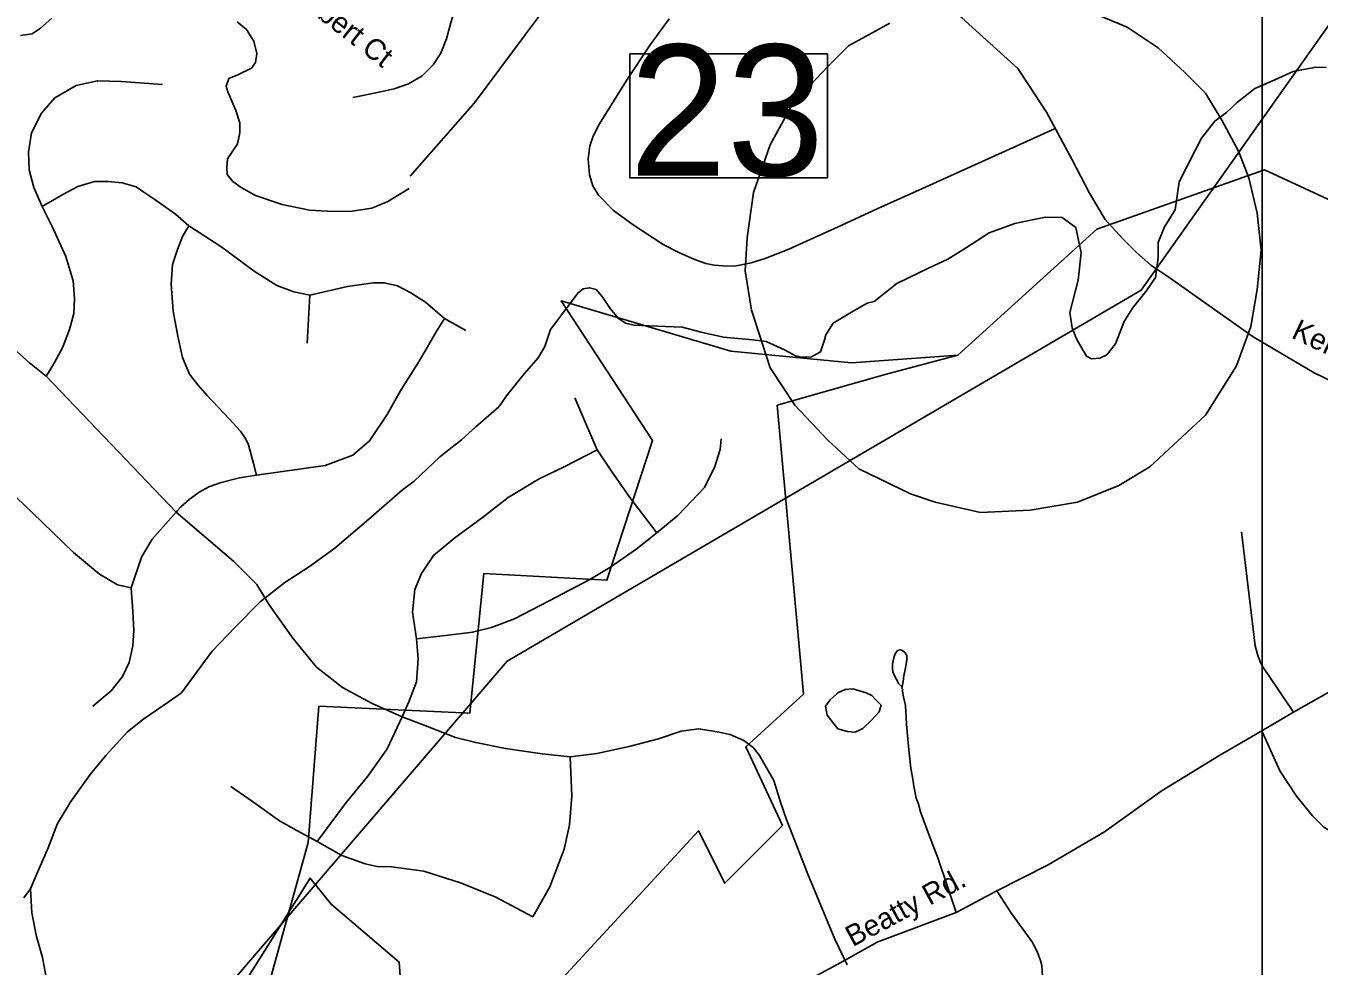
# Model space of a CAD drawing. Extents: x 1268485 to 1426702, y 514839 to 616766.
# Drawn here: x 1364164 to 1368211, y 535006 to 537948 of the extents above; entities that cross this region are included whole.
import ezdxf

# ---------------------------------------------------------------- set-up
doc = ezdxf.new("R2010")
doc.units = 0
for name, color, linetype in [('Old_Level_10', 7, 'Continuous'), ('Old_Level_11', 7, 'Continuous'), ('Old_Level_3', 7, 'Continuous'), ('Old_Level_31', 7, 'Continuous'), ('Old_Level_32', 7, 'Continuous'), ('Old_Level_35', 7, 'Continuous'), ('Old_Level_48', 7, 'Continuous'), ('Old_Level_49', 7, 'Continuous'), ('Old_Level_50', 7, 'Continuous'), ('Old_Level_56', 7, 'Continuous'), ('Old_Level_59', 7, 'Continuous'), ('Old_Level_62', 7, 'Continuous'), ('Old_Level_63', 7, 'Continuous')]:
    doc.layers.add(name, color=color, linetype=linetype)

msp = doc.modelspace()

# ---------------------------------------------------------------- linework, layer by layer
at = {"layer": 'Old_Level_3'}
for points in [[(1367151.529, 536425.852), (1367306.529, 536432.31), (1367455.071, 536458.143), (1367584.237, 536509.81), (1367681.112, 536567.935), (1367855.487, 536729.394), (1367952.362, 536884.393), (1367997.57, 537007.102), (1368016.945, 537123.352), (1368029.862, 537246.06), (1368016.945, 537362.31), (1367991.112, 537472.102), (1367958.821, 537556.06), (1367907.154, 537652.935), (1367855.487, 537736.893), (1367790.903, 537801.477), (1367706.945, 537878.977), (1367610.07, 537943.56), (1367487.362, 537995.227)], [(1366867.362, 537956.477), (1366738.195, 537885.436), (1366673.612, 537820.852), (1366563.82, 537704.602), (1366492.778, 537575.435), (1366441.112, 537426.893), (1366421.737, 537284.81), (1366415.279, 537181.477), (1366434.654, 537058.769), (1366492.778, 536877.935), (1366570.278, 536761.685), (1366673.612, 536651.894), (1366770.487, 536561.477), (1366931.945, 536483.977), (1367009.445, 536458.143), (1367151.529, 536425.852)]]:
    msp.add_lwpolyline(points, dxfattribs=at)
at = {"layer": 'Old_Level_31'}
msp.add_line((1367691.483, 537149.381), (1367691.483, 537149.381), dxfattribs=at)
msp.add_lwpolyline([(1366054.207, 537860.024), (1366672.4, 537860.024), (1366672.4, 537472.278), (1366054.207, 537472.278), (1366054.207, 537860.024)], dxfattribs=at)
at = {"layer": 'Old_Level_32'}
for points in [[(1366801.236, 538688.336), (1366842.188, 538636.437), (1366864.029, 538581.806), (1366880.409, 538529.908), (1366896.528, 538459.074), (1366921.223, 538360.896), (1367003.265, 538115.264), (1367060.596, 538014.198), (1367093.358, 537973.226), (1367268.085, 537814.798), (1367300.847, 537765.63), (1367358.179, 537678.222), (1367438.695, 537528.693), (1367492.959, 537424.647), (1367541.267, 537342.316), (1367596.733, 537281.462), (1367639.674, 537238.507), (1367684.405, 537199.131), (1367738.082, 537163.335), (1368004.675, 536975.405), (1368196.122, 536862.648), (1368550.387, 536690.827)], [(1368032.196, 535742.385), (1368131.081, 535800.326), (1368518.18, 536019.65), (1368682.789, 536123.459), (1368857.781, 536236.815), (1368986.956, 536304.229), (1369144.407, 536366.872)], [(1365594.581, 533858.966), (1365633.814, 533978.307), (1365703.731, 534164.402), (1365780.174, 534337.58), (1365829.316, 534394.941), (1365957.631, 534523.323), (1366031.345, 534591.611), (1366119.804, 534655.853), (1366294.364, 534767.215), (1366397.179, 534830.892), (1366511.844, 534908.466), (1366716.603, 535018.273), (1366828.537, 535081.098), (1367075.166, 535174.199), (1367202.093, 535241.559), (1367362.744, 535323.022), (1367539.267, 535426.681), (1367719.543, 535555.778), (1367897.204, 535664.131), (1368032.196, 535742.385)], [(1368032.196, 535742.385), (1368088.056, 535617.479), (1368140.812, 535537.72), (1368190.464, 535476.019), (1368226.151, 535441.407), (1368333.99, 535373.687), (1368392.086, 535351.796), (1368646.22, 535319.314), (1368699.442, 535308.664), (1368871.632, 535257.81), (1368904.351, 535252.751), (1369097.396, 535251.79), (1369325.118, 535237.506), (1369411.734, 535235.561), (1369491.515, 535226.767), (1369594.917, 535196.839), (1369696.041, 535159.563), (1369821.114, 535119.626), (1369969.236, 535063.895), (1370088.099, 535002.314)]]:
    msp.add_lwpolyline(points, dxfattribs=at)
at = {"layer": 'Old_Level_35'}
for p, q in [((1365052.84, 537105.02), (1365044.33, 536954.666)), ((1365473.914, 537032.637), (1365540.864, 536995.01)), ((1364228.018, 536851.833), (1364634.636, 536426.452))]:
    msp.add_line(p, q, dxfattribs=at)
for points in [[(1365596.535, 538152.991), (1365583.617, 538138.637), (1365559.216, 538108.392), (1365537.173, 538073.481), (1365523.742, 538046.312), (1365510.208, 538012.683), (1365495.239, 537961.575), (1365480.886, 537907.492), (1365462.329, 537862.38), (1365438.953, 537826.24), (1365403.889, 537791.586), (1365361.34, 537766.775), (1365316.332, 537751.089), (1365269.272, 537740.631), (1365187.661, 537723.612)], [(1366177.55, 537970.187), (1366117.778, 537888.73), (1366043.754, 537777.386), (1365958.862, 537641.232), (1365939.587, 537602.989), (1365929.232, 537572.181), (1365924.208, 537532.196), (1365928.002, 537481.65), (1365938.46, 537447.765), (1365956.299, 537418.187), (1366002.538, 537370.102), (1366064.156, 537325.196), (1366158.378, 537263.577), (1366206.975, 537238.304), (1366254.547, 537218.004), (1366291.457, 537204.42), (1366317.908, 537199.499), (1366346.206, 537196.986), (1366381.987, 537196.423), (1366433.763, 537206.265), (1366477.541, 537220.414), (1366551.36, 537249.377), (1366717.145, 537324.58), (1366829.923, 537376.92), (1366970.282, 537439.102), (1367382.744, 537625.802)], [(1364591.985, 537764.007), (1364463.417, 537773.952), (1364387.958, 537776.105), (1364321.624, 537761.751), (1364255.084, 537722.997), (1364213.151, 537674.245), (1364182.086, 537613.396), (1364172.141, 537552.496), (1364174.396, 537497.132), (1364188.75, 537441.818), (1364214.997, 537382.763)], [(1364214.997, 537382.763), (1364279.998, 537419.775), (1364326.853, 537445.817), (1364379.141, 537461.453), (1364420.767, 537461.453), (1364465.673, 537456.275), (1364509.452, 537443.766), (1364533.545, 537428.08), (1364564.918, 537407.165), (1364632.585, 537359.183), (1364674.416, 537322.683)], [(1364214.997, 537382.763), (1364246.985, 537318.326), (1364288.918, 537226.206), (1364312.089, 537149.927), (1364316.498, 537094.82), (1364314.345, 537048.426), (1364300.606, 536997.932), (1364278.46, 536940.569), (1364253.547, 536894.176), (1364240.423, 536872.081), (1364228.018, 536851.833)], [(1364674.416, 537322.683), (1364654.628, 537288.747), (1364638.327, 537248.454), (1364622.743, 537201.754), (1364618.539, 537140.187), (1364625.614, 537055.244), (1364639.762, 536977.427), (1364654.628, 536910.17), (1364676.467, 536858.548), (1364702.713, 536824.612), (1364731.01, 536791.393), (1364766.382, 536755.304), (1364800.42, 536718.497), (1364835.792, 536679.537), (1364851.273, 536656.931), (1364860.501, 536637.143), (1364876.7, 536578.396), (1364885.415, 536542.46)], [(1364674.416, 537322.683), (1364774.481, 537257.374), (1364878.648, 537180.582), (1364949.493, 537135.317), (1365002.397, 537115.683), (1365052.84, 537105.02)], [(1363811.147, 537143.673), (1363841.494, 537124.039), (1363915.416, 537082.926), (1364020.402, 537022.897), (1364077.099, 536980.4), (1364176.037, 536893.817), (1364228.018, 536851.833)], [(1365052.84, 537105.02), (1365170.54, 537132.549), (1365250.51, 537144.288), (1365285.779, 537144.288), (1365326.892, 537134.958), (1365369.235, 537112.557), (1365415.167, 537083.182), (1365473.914, 537032.637)], [(1365473.914, 537032.637), (1365447.975, 536990.294), (1365424.497, 536949.181), (1365395.174, 536898.585), (1365337.452, 536808.054), (1365295.109, 536731.621), (1365239.847, 536649.292), (1365187.046, 536604.643), (1365101.129, 536572.859), (1364885.415, 536542.46)], [(1365882.378, 536783.756), (1365915.084, 536706.297), (1365952.403, 536621.354)], [(1366339.746, 536655.649), (1366336.773, 536622.892), (1366320.369, 536569.169), (1366287.663, 536503.705), (1366205.642, 536417.276), (1366138.59, 536362.117)], [(1365952.403, 536621.354), (1365848.134, 536567.733), (1365770.624, 536530.516), (1365673.84, 536472.384), (1365593.357, 536409.791), (1365507.03, 536345.764), (1365439.875, 536290.605), (1365402.658, 536234.011), (1365381.743, 536184.798), (1365374.361, 536113.338), (1365386.254, 536029.932)], [(1365952.403, 536621.354), (1365997.104, 536554.302), (1366053.801, 536472.384), (1366138.59, 536362.117)], [(1364083.866, 536520.879), (1364184.752, 536424.812), (1364312.909, 536299.935), (1364394.52, 536232.678), (1364450.499, 536199.1), (1364493.765, 536189.515)], [(1364885.415, 536542.46), (1364832.614, 536533.387), (1364774.892, 536519.392), (1364736.957, 536505.295), (1364706.404, 536488.891), (1364675.134, 536465.822), (1364648.784, 536443.522), (1364639.045, 536431.834), (1364634.636, 536426.452)], [(1364634.636, 536426.452), (1364559.382, 536341.561), (1364525.753, 536285.581), (1364493.765, 536189.515)], [(1364634.636, 536426.452), (1364815.287, 536272.561), (1364886.747, 536199.665), (1364926.015, 536136.816), (1364999.629, 536031.727), (1365073.242, 535940.991), (1365155.366, 535878.143), (1365248.254, 535827.443), (1365341.758, 535786.587)], [(1366138.59, 536362.117), (1366073.076, 536309.983), (1365991.158, 536253.388), (1365928.617, 536216.12), (1365801.997, 536149.068), (1365693.115, 536092.422), (1365621.654, 536065.663), (1365562.086, 536050.745), (1365477.092, 536040.288), (1365386.254, 536029.932)], [(1368131.081, 535800.326), (1368032.862, 535945.4), (1368026.095, 535961.24), (1368019.841, 535977.696), (1368011.331, 536007.838), (1367998.925, 536112.825), (1367968.27, 536364.834)], [(1364493.765, 536189.515), (1364498.481, 536115.901), (1364501.762, 536056.641), (1364498.481, 536008.556), (1364487.408, 535955.755), (1364466.493, 535912.54), (1364431.224, 535867.685), (1364373.605, 535819.703)], [(1365386.254, 536029.932), (1365392.201, 535967.289), (1365386.254, 535895.828), (1365362.468, 535833.237), (1365341.758, 535786.587)], [(1366906.715, 535880.244), (1366909.176, 535897.008), (1366911.637, 535914.54), (1366915.533, 535933.712), (1366918.711, 535950.424), (1366921.172, 535965.546), (1366921.172, 535978.362), (1366915.533, 535986.308), (1366907.638, 535993.485), (1366899.641, 535995.894), (1366891.644, 535993.485), (1366886.005, 535985.488), (1366881.289, 535975.133), (1366878.111, 535961.65), (1366875.65, 535950.424), (1366875.65, 535938.428), (1366877.291, 535926.484), (1366882.007, 535914.54), (1366888.466, 535902.544), (1366896.36, 535889.831), (1366906.715, 535880.244)], [(1367075.166, 535174.199), (1367047.996, 535255.707), (1367018.469, 535345.008), (1366992.12, 535412.828), (1366972.23, 535466.244), (1366964.233, 535489.364), (1366956.953, 535512.483), (1366950.597, 535531.707), (1366946.598, 535548.419), (1366942.6, 535569.129), (1366939.524, 535590.711), (1366933.885, 535625.826), (1366926.708, 535683.189), (1366920.351, 535763.006), (1366916.353, 535822.01), (1366910.714, 535849.128), (1366907.638, 535865.891), (1366906.715, 535880.244)], [(1365341.758, 535786.587), (1365294.801, 535686.317), (1365233.901, 535600.708), (1365166.336, 535518.482), (1365075.293, 535395.809)], [(1365341.758, 535786.587), (1365421.113, 535755.829), (1365508.26, 535721.176), (1365572.339, 535705.797), (1365664.613, 535686.624), (1365779.852, 535669.963), (1365866.999, 535660.993)], [(1365866.999, 535660.993), (1365950.865, 535671.399), (1366051.546, 535693.442), (1366143.614, 535716.818), (1366214.767, 535741.322), (1366270.029, 535748.703), (1366327.648, 535738.861), (1366368.146, 535730.3), (1366411.105, 535711.897), (1366440.53, 535689.803), (1366460.112, 535665.247), (1366504.711, 535587.327)], [(1365866.999, 535660.993), (1365873.15, 535537.449), (1365865.051, 535448.302), (1365848.852, 535372.177), (1365803.535, 535253.913), (1365750.529, 535160.051)], [(1366733.959, 535009.952), (1366695.717, 535090.384), (1366611.03, 535294.308), (1366544.286, 535464.861), (1366526.651, 535516.329), (1366504.711, 535587.327)], [(1364805.957, 535568.053), (1364873.624, 535520.737), (1364958.003, 535461.067), (1365012.137, 535430.668), (1365075.293, 535395.809)], [(1365075.293, 535395.809), (1365152.905, 535351.825), (1365226.006, 535325.938), (1365263.223, 535318.043), (1365308.232, 535316.915), (1365409.63, 535303.433), (1365524.459, 535266.268), (1365634.88, 535222.335), (1365750.529, 535160.051)], [(1367202.093, 535241.559), (1367248.025, 535170.354), (1367315.282, 535078.798), (1367330.251, 535048.553), (1367339.375, 535023.639), (1367343.271, 535007.799), (1367345.629, 534974.017), (1367342.041, 534944.387), (1367326.15, 534889.792), (1367300.415, 534822.74), (1367297.545, 534815.05)]]:
    msp.add_lwpolyline(points, dxfattribs=at)
at = {"layer": 'Old_Level_48'}
msp.add_lwpolyline([(1364733.21, 534260.538), (1365047.846, 535392.457), (1365080.825, 535818.954), (1365553.521, 535797.629), (1365597.492, 536234.789), (1365982.245, 536213.464), (1366125.153, 536650.623), (1365839.337, 537087.784), (1366370.377, 536930.415), (1366747.642, 536893.202), (1367080.147, 536918.01), (1367515.757, 537311.694), (1368040.129, 537497.536), (1369605.755, 536773.069), (1369669.627, 536589.051), (1370316.47, 537169.674), (1370455.511, 537381.36), (1370497.828, 537623.286), (1370800.091, 537550.709), (1371084.218, 537387.408), (1371277.666, 537399.505)], dxfattribs=at)
at = {"layer": 'Old_Level_49'}
for points in [[(1365480.561, 534575.023), (1366269.05, 535429.71), (1366351.184, 535265.347), (1366531.879, 535446.147), (1366416.892, 535692.691), (1366597.587, 535857.054), (1366515.453, 536761.05), (1366860.417, 536859.667), (1367080.147, 536918.01), (1367515.757, 537311.694), (1368040.129, 537497.536), (1369605.755, 536773.069), (1369669.627, 536589.051), (1370316.47, 537169.674), (1370455.511, 537381.36), (1370497.828, 537623.286), (1370800.091, 537550.709), (1371084.218, 537387.408), (1371277.666, 537399.505)], [(1364494.95, 534390.114), (1365053.463, 535281.783), (1365119.171, 535199.602), (1365332.719, 535018.803), (1365349.146, 534788.695)]]:
    msp.add_lwpolyline(points, dxfattribs=at)
at = {"layer": 'Old_Level_50'}
msp.add_line((1367708.342, 537193.76), (1367708.342, 537193.76), dxfattribs=at)
at = {"layer": 'Old_Level_56'}
msp.add_lwpolyline([(1365744.307, 534249.532), (1365626.185, 534264.849), (1365378.693, 534304.855), (1365321.976, 534312.355), (1365262.682, 534312.355), (1365218.855, 534347.361), (1365212.106, 534364.106), (1365155.074, 534413.477), (1365046.812, 534507.964), (1364683.675, 534810.705), (1365669.85, 535960.316), (1367654.342, 537120.566), (1368839.882, 538796.482), (1371236.735, 540446.616)], dxfattribs=at)
at = {"layer": 'Old_Level_59'}
for points in [[(1365366.979, 537478.113), (1365567.93, 537707.105), (1365884.941, 538134.023), (1365937.947, 538283.967), (1365988.902, 538332.155), (1366130.901, 538339.126), (1366222.969, 538379.932), (1366359.944, 538508.499), (1366637.995, 538660.443), (1366774.97, 538851.347), (1366778.276, 538910.128), (1366708.707, 538986.375), (1366657.254, 539079.746), (1366665.784, 539186.45), (1366667.802, 539248.467), (1366623.443, 539263.832), (1366584.746, 539378.518), (1366623.133, 539425.469), (1366822.202, 539607.848), (1366978.308, 539636.018)], [(1364244.934, 537971.725), (1364210.281, 537940.403), (1364183.829, 537922.871), (1364147.74, 537917.847)], [(1365363.801, 537438.743), (1365296.852, 537398.245), (1365246.409, 537377.125), (1365178.126, 537367.026), (1365108.101, 537368.41), (1365052.224, 537371.178), (1364966.513, 537389.325), (1364883.056, 537417.264), (1364837.637, 537441.973), (1364812.006, 537460.53), (1364794.577, 537483.034), (1364793.039, 537503.591), (1364795.602, 537531.426), (1364826.565, 537578.435), (1364833.331, 537612.729), (1364834.049, 537644.718), (1364820.926, 537682.755), (1364796.217, 537741.502), (1364790.578, 537759.701), (1364799.19, 537783.282), (1364827.385, 537794.2), (1364869.831, 537815.526), (1364882.236, 537833.315), (1364886.85, 537861.15), (1364877.725, 537899.905), (1364854.554, 537936.456), (1364825.129, 537960.857)]]:
    msp.add_lwpolyline(points, dxfattribs=at)
at = {"layer": 'Old_Level_62'}
for points in [[(1368232.751, 537818.899), (1368195.328, 537817.887), (1368129.585, 537804.73), (1368072.945, 537779.426), (1368010.237, 537752.098), (1367955.62, 537709.589), (1367921.233, 537676.998), (1367884.821, 537649.671), (1367843.353, 537597.04), (1367802.896, 537517.082), (1367773.564, 537459.39), (1367760.245, 537372.46), (1367727.039, 537319.308), (1367707.823, 537269.713), (1367707.823, 537222.144), (1367698.72, 537160.403), (1367670.4, 537117.894), (1367627.594, 537064.589), (1367600.63, 537022.503), (1367573.545, 536952.821), (1367546.786, 536918.885), (1367524.537, 536907.812), (1367498.393, 536905.915), (1367482.707, 536914.425), (1367465.277, 536944.311), (1367451.846, 536969.225), (1367437.941, 537003.432), (1367430.969, 537051.157), (1367457.544, 537152.125), (1367466.646, 537238.157), (1367449.451, 537317.103), (1367406.972, 537348.48), (1367354.544, 537348.879), (1367317.966, 537342.407), (1367259.303, 537329.249), (1367178.389, 537299.897), (1367104.555, 537252.327), (1367048.927, 537217.914), (1366989.252, 537189.574), (1366889.88, 537141.498), (1366819.08, 537085.83), (1366796.323, 537080.769), (1366747.695, 537051.636), (1366690.122, 537017.511), (1366667.955, 536980.92), (1366662.308, 536961.843), (1366657.251, 536946.662), (1366650.503, 536927.907), (1366622.206, 536912.066), (1366592.166, 536910.99), (1366572.276, 536915.501), (1366538.647, 536934.264), (1366481.13, 536960.818), (1366439.197, 536965.79), (1366347.436, 536974.197), (1366277.616, 536989.576), (1366217.946, 537004.699), (1366139.923, 537007.928), (1366068.052, 537011.824), (1366040.165, 537018.13), (1366018.43, 537032.535), (1365993.106, 537063.395), (1365967.782, 537101.637), (1365948.302, 537122.552), (1365928.309, 537128.704), (1365908.214, 537125.013), (1365892.015, 537113.017), (1365856.951, 537066.112), (1365805.586, 536997.42)], [(1365805.586, 536997.42), (1365788.464, 536945.234), (1365767.651, 536909.555), (1365724.693, 536860.342), (1365671.174, 536794.161), (1365644.21, 536756.124), (1365572.442, 536693.533), (1365527.228, 536652.625), (1365459.458, 536599.824), (1365379.59, 536523.493), (1365342.988, 536496.323)], [(1365342.988, 536496.323), (1365236.976, 536404.87), (1365130.862, 536313.469), (1365051.609, 536256.823), (1364974.51, 536206.636), (1364897.103, 536145.838), (1364819.285, 536066.176), (1364747.62, 535991.28), (1364700.253, 535928.227), (1364650.732, 535861.124), (1364612.08, 535834.005), (1364532.93, 535779.821), (1364481.975, 535738.963), (1364414.307, 535664.837), (1364364.992, 535605.936), (1364305.117, 535520.993), (1364263.492, 535452.045), (1364233.862, 535376.329), (1364197.977, 535294.975), (1364179.01, 535247.761)], [(1366751.901, 535874.045), (1366793.527, 535860.922), (1366811.469, 535852.361), (1366823.054, 535840.622), (1366840.791, 535822.219), (1366834.435, 535801.816), (1366811.776, 535776.851), (1366783.172, 535749.528), (1366758.975, 535737.686), (1366734.984, 535739.839), (1366705.252, 535748.605), (1366685.772, 535772.801), (1366672.033, 535791.153), (1366666.702, 535819.963), (1366681.056, 535839.391), (1366705.559, 535861.024), (1366727.705, 535872.097), (1366751.901, 535874.045)], [(1364179.01, 535247.761), (1364158.3, 535220.284)], [(1364179.01, 535247.761), (1364183.316, 535173.02), (1364197.772, 535098.893), (1364216.33, 535032.867), (1364237.758, 534914.244)]]:
    msp.add_lwpolyline(points, dxfattribs=at)
at = {"layer": 'Old_Level_63'}
msp.add_lwpolyline([(1305516.95, 558564.883), (1305516.95, 529802.059), (1368033.021, 529802.059), (1368033.021, 573241.255), (1305516.95, 573241.255), (1305516.95, 558564.883)], dxfattribs=at)

# ---------------------------------------------------------------- texts
at = {"layer": 'Old_Level_10'}
msp.add_text('Trabert Ct', height=65.6167, rotation=322.108258, dxfattribs=at).set_placement((1364968.907, 538057.391))
at = {"layer": 'Old_Level_11'}
for s, height, rotation, p in [('Kendrick Rd.', 65.61666, 334.497044, (1368121.032, 536973.582)), ('Beatty Rd.', 65.6167, 28.313042, (1366751.604, 535065.058))]:
    msp.add_text(s, height=height, rotation=rotation, dxfattribs=at).set_placement(p)
at = {"layer": 'Old_Level_31'}
msp.add_text('23', height=410.1042, dxfattribs=at).set_placement((1366052.547, 537478.804))

doc.saveas('drawing.dxf')
